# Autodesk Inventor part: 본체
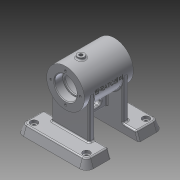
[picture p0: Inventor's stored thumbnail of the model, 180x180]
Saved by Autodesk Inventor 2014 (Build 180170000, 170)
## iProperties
Created: 2016-07
Part Number: 본체
Material: 알루미늄 6061
Document SubType Name: Modeling
Designer: user
Density: 2.71 g/cm^3
Appearance: 알루미늄 - 평지
Mass: 498.568 g
Surface Area: 541.961 cm^2
Volume: 183.973 cm^3
Author: user
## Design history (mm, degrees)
sketch "스케치1"
  geometry: C1 r 27 at (0, 0); 1 further point
  constraints: 1 centre point, 1 coincident
  dimensions: "d0" = 54 diameter of C1
extrude "돌출1" new body sketch "스케치1" stored distance "d1" = 70; taper "d2" = 0 deg
hole "구멍1" diameter "d5" = 28; stored, may be unused: countersink angle "d9" = 90 deg, drill point angle "d11" = 0 deg; dims "d6" = 6, "d7" = 32, "d8" = 12, "d10" = 14, "d12" = 10, "d13" = 10
sketch "스케치2"
  geometry: C1 r 16 at (0, 0) reference; 1 further point
  constraints: 1 vertical alignment
  dimensions: "d23" = 21 distance of point (0, 21) C1.centre
hole "구멍3" sketch "스케치2" at (0, 21) diameter "d24" = 3.242; stored, may be unused: countersink angle "d28" = 90 deg, drill point angle "d30" = 118 deg; dims "d25" = 8, "d26" = 32, "d27" = 12, "d29" = 10
node "작업 평면1"
sketch "스케치4"
  geometry: L1 (40, 55)-(-40, 55); L2 (-50, 45)-(-50, -45); L3 (-40, -55)-(40, -55); L4 (50, -45)-(50, 45); L5 (50, 55)-(-50, -55); L6 (-50, 55)-(50, -55); A1 r 10 centre (-40, 45) between (-40, 55) and (-50, 45); A2 r 10 centre (40, 45) between (50, 45) and (40, 55); A3 r 10 centre (40, -45) between (40, -55) and (50, -45); A4 r 10 centre (-40, -45) between (-50, -45) and (-40, -55); 1 further point
  constraints: 12 end point, 8 point on circle, 8 point on line, 8 tangent, 4 centre point, 3 equal radius, 2 midpoint, 2 parallel, 1 horizontal, 1 perpendicular
  dimensions: "d39" = 100 distance of L6.end L5.end; "d40" = 110 distance of L5.end L6.start; "d41" = 10 radius of A1
extrude "돌출2" join sketch "스케치4" distance "d42" = 12; taper "d43" = -20 deg
sketch "스케치5"
  geometry: L1 (-51.967, 20)-(51.967, 20); L2 (51.967, 20)-(51.967, -20); L3 (51.967, -20)-(-51.967, -20); L4 (-51.967, -20)-(-51.967, 20); L5 (-51.967, 20)-(51.967, -20); L6 (51.967, 20)-(-51.967, -20); L7 (-40, 55)-(40, 55) reference; 1 further point
  constraints: 12 end point, 2 midpoint, 2 parallel, 1 horizontal, 1 perpendicular
  dimensions: "d44" = 35 distance between parallel lines of L1 L7
extrude "돌출3" cut sketch "스케치5" stored distance "d45" = 12; taper "d46" = 0 deg
sketch "스케치6"
  geometry: L1 (45.632, -20)-(-45.632, -20) reference; L2 (-27, -20)-(27, -20); L3 (27, -20)-(27, -28); L4 (27, -28)-(-27, -28); L5 (-27, -28)-(-27, -20); 1 further point
  constraints: 8 end point, 2 parallel, 2 point on line, 1 perpendicular
  dimensions: "d47" = 54 distance between parallel lines of L3 L5; "d48" = 8 distance between parallel lines of L1 L4; "d49" = 27 distance from line of L5 point (0, 0)
extrude "돌출4" join sketch "스케치6" stored distance "d50" = 12; taper "d51" = 0 deg
sketch "스케치7"
  geometry: L1 (27, 28)-(27, 20) reference; L2 (27, 20)-(45.632, 20) reference; L3 (45.632, 45)-(45.632, 20) reference; L4 (-40, 50.632)-(40, 50.632) reference; L5 (-45.632, 20)-(-45.632, 45) reference; L6 (-45.632, 20)-(-27, 20) reference; L7 (-27, 20)-(-27, 28) reference; L8 (-27, 28)-(27, 28) reference; A1 r 5.632 centre (40, 45) between (45.632, 45) and (40, 50.632) reference; A2 r 5.632 centre (-40, 45) between (-40, 50.632) and (-45.632, 45) reference; 5 further points
  constraints: 2 horizontal alignment, 2 vertical alignment
  dimensions: "d52" = 85 distance of point (-37.5, -42.5) point (-37.5, 42.5); "d53" = 75 distance of point (37.5, -42.5) point (-37.5, -42.5); "d54" = 37.5 horizontal distance of point (-37.5, -42.5) point (0, 0); "d55" = 42.5 vertical distance of point (0, 0) point (-37.5, 42.5)
hole "구멍4" sketch "스케치7" at (-37.5, 42.5), (37.5, 42.5), (37.5, -42.5), (-37.5, -42.5) diameter "d56" = 6; stored, may be unused: countersink angle "d60" = 90 deg, drill point angle "d62" = 0 deg; dims "d57" = 8, "d58" = 10, "d59" = 4, "d61" = 10
sketch "스케치8"
  geometry: L1 (-20, -24.885)-(20, -24.885); L2 (20, -24.885)-(20, -48); L3 (20, -48)-(-20, -48); L4 (-20, -48)-(-20, -24.885); L5 (-20, -58)-(-20, 0) reference; L6 (20, -58)-(20, 0) reference; L7 (-35, -27)-(35, -27) reference; L8 (-8, -38)-(8, -38); L9 (-8, -41.5)-(8, -41.5); L10 (8, -34.5)-(-8, -34.5); L11 (45.5, -70)-(39.5, -70) reference; A1 r 3.5 centre (-8, -38) between (-8, -34.5) and (-8, -41.5); A2 r 3.5 centre (8, -38) between (8, -41.5) and (8, -34.5); 2 further points
  constraints: 16 end point, 4 parallel, 4 point on circle, 4 tangent, 2 centre point, 2 collinear, 1 horizontal, 1 midpoint, 1 perpendicular, 1 vertical alignment
  dimensions: "d63" = 21 distance between parallel lines of L7 L3; "d64" = 7 diameter of A2; "d65" = 23 dimension on A2 A1; "d66" = 32 distance from line of point (0, -38) L11
extrude "돌출5" join sketch "스케치8" stored distance "d67" = 8; taper "d68" = 0 deg
hole "구멍6" diameter "d85" = 28; stored, may be unused: countersink angle "d89" = 90 deg, drill point angle "d91" = 0 deg; dims "d83" = 10, "d84" = 10, "d86" = 8, "d87" = 32, "d88" = 12, "d90" = 14
sketch "스케치9"
  geometry: C1 r 14 at (0, 0) reference; C2 r 22 at (0, 0)
  constraints: 1 centre point, 1 coincident
  dimensions: "d92" = 44 diameter of C2
extrude "돌출6" cut sketch "스케치9" distance "d93" = 42; taper "d94" = 0 deg
chamfer "모따기1" distance "d69" = 1; stored, may be unused: second distance "d70" = 2, angle "d71" = 45 deg
fillet "모깎기1" dims "d95" = 0.3
fillet "모깎기2" dims "d96" = 2
fillet "모깎기3" dims "d97" = 2
fillet "모깎기4" dims "d98" = 2
fillet "모깎기5" dims "d99" = 2
fillet "모깎기6" dims "d100" = 2
fillet "모깎기7" dims "d101" = 2
fillet "모깎기8" dims "d102" = 2
fillet "모깎기9" dims "d103" = 2
fillet "모깎기10" dims "d104" = 2
node "작업 평면2"
sketch "스케치10"
  geometry: L1 (-35, 27)-(35, 27) reference; L2 (-35, 27)-(-35, -27) reference; 2 further points
  constraints: 1 other
  dimensions: "d106" = 27 distance from line of point (0, 0) L1; "d107" = 35 distance from line of point (0, 0) L2
feature "엠보싱1" sketch "스케치10" dims "d39" = 100, "d40" = 110, "d41" = 10, "d108" = 0.5, "d109" = 0
node "작업 평면3"
sketch "스케치11"
  geometry: L1 (-27, -35)-(27, -35) reference; C1 r 5 at (0, -13); 1 further point
  constraints: 1 centre point, 1 vertical alignment
  dimensions: "d111" = 10 diameter of C1; "d112" = 22 distance from line of C1.centre L1
extrude "돌출7" join sketch "스케치11" stored distance "d113" = 42; taper "d114" = 0 deg
sketch "스케치12"
  geometry: L1 (0, 0)-(0, -80.432); L2 (0, 0)-(15.898, -25.441); C1 r 27 at (0, 0) reference; 2 further points
  constraints: 4 end point, 1 coincident, 1 vertical
  dimensions: "d115" = 32 deg angle of L2 L1; "d116" = 30 distance of L1.start L2.end
node "작업 평면4"
sketch "스케치13"
  geometry: C1 r 6 at (0, 0); 2 further points
  constraints: 1 centre point, 1 coincident
  dimensions: "d117" = 12 diameter of C1
extrude "돌출8" join sketch "스케치13" stored distance "d118" = 42; taper "d119" = 0 deg
hole "구멍7" diameter "d122" = 4.917; stored, may be unused: countersink angle "d126" = 90 deg, drill point angle "d128" = 118 deg; dims "d120" = 10, "d121" = 10, "d123" = 20, "d124" = 32, "d125" = 12, "d127" = 20
hole "구멍8" diameter "d131" = 4.917; stored, may be unused: countersink angle "d135" = 90 deg, drill point angle "d137" = 118 deg; dims "d129" = 10, "d130" = 10, "d132" = 20, "d133" = 32, "d134" = 12, "d136" = 20
fillet "모깎기11" dims "d138" = 2
node "솔리드1"
pattern_circular "원형 패턴1" dims angle "d32" = 360 deg
mirror "대칭3"
mirror "대칭4"
node "투영된 루프1"
other parameters: "d105" = 27
